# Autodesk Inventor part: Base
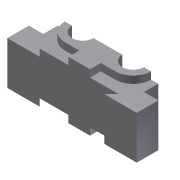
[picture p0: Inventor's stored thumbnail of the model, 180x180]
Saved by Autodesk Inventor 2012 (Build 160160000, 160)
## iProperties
Created: 2009-05
Part Number: Base
Document SubType Name: Modeling
Designer: Sham
Density: 1 g/cm^3
Material: Default
Author: Sham
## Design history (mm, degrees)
sketch "Sketch1"
  geometry: L1 (0, 0)-(27.5, 0); L2 (27.5, 0)-(22.5, -5); L3 (22.5, -5)-(45, -5); L4 (45, -5)-(45, 10); L5 (45, 10)-(35, 10); L6 (35, 10)-(35, 20); L7 (35, 20)-(-35, 20); L8 (-35, 20)-(-35, 10); L9 (-35, 10)-(-45, 10); L10 (-45, 10)-(-45, -5); L11 (-45, -5)-(-22.5, -5); L12 (-22.5, -5)-(-27.5, 0); L13 (-27.5, 0)-(0, 0); 1 further point
  constraints: 26 end point, 9 perpendicular, 5 equal length, 2 horizontal, 1 coincident, 1 other
  dimensions: "d1" = 15 distance of L9.end L10.end; "d2" = 5 distance between parallel lines of L11 L13; "d3" = 10 distance of L5.end L6.end; "d4" = 22.5 distance of L2.end L3.end; "d5" = 45 distance of L2.end L11.end; "d6" = 90 distance between parallel lines of L4 L10 (derived); "d7" = 5 horizontal distance of L1.end L2.end; "d15" = 70 distance of L6.end L7.end; "d16" = 35 distance from line of L8 point (0, 0)
extrude "Extrusion1" new body sketch "Sketch1" stored distance "d8" = 30; taper "d9" = 0 deg
sketch "Sketch2"
  geometry: L1 (-7.5, 0)-(-7.5, 7.5); L2 (-7.5, 7.5)-(-17.5, 7.5); L3 (7.5, 7.5)-(17.5, 7.5); L4 (7.5, 0)-(7.5, 7.5); L5 (-7.5, 0)-(7.5, 0); L6 (35, 20)-(-35, 20) reference; L7 (-30, 20)-(30, 20); A1 r 12.5 centre (-17.5, 20) between (-30, 20) and (-17.5, 7.5); A2 r 12.5 centre (17.5, 20) between (17.5, 7.5) and (30, 20); 2 further points
  constraints: 12 end point, 4 point on circle, 3 perpendicular, 2 centre point, 2 horizontal, 2 point on line, 2 tangent, 1 coincident, 1 collinear, 1 horizontal alignment, 1 midpoint, 1 other
  dimensions: "d10" = 15 distance of L1.start L4.start; "d11" = 35 distance of A2.centre A1.centre; "d12" = 12.5 radius of A1; "d13" = 12.5 radius of A2; "d14" = 7.5 distance of L1.start L1.end
extrude "Extrusion2" join sketch "Sketch2" stored distance "d17" = 40; taper "d18" = 0 deg
sketch "Sketch3"
  geometry: L1 (10, 20)-(10.397, 20); L2 (10, 20)-(25, 20); L3 (-25, 20)-(-10, 20); L4 (-30, 20)-(30, 20) reference; A1 r 7.5 centre (-17.5, 20) between (-25, 20) and (-10, 20); A2 r 7.5 centre (17.5, 20) between (10, 20) and (25, 20); A3 r 12.5 centre (17.5, 20) between (17.5, 7.5) and (30, 20) reference; A4 r 12.5 centre (-17.5, 20) between (-30, 20) and (-17.5, 7.5) reference; 2 further points
  constraints: 6 end point, 4 point on circle, 3 coincident, 2 centre point, 2 horizontal, 2 midpoint, 2 point on line, 1 equal radius
  dimensions: "d19" = 15 diameter of A1; "d53" = 7.5 radius of A2 (derived); "d54" = 35 distance of A1.centre A3.centre (derived)
extrude "Extrusion3" cut sketch "Sketch3" distance "d24" = 40; taper "d25" = 0 deg
hole "Hole1" diameter "d28" = 4.5; stored, may be unused: countersink angle "d32" = 90 deg, drill point angle "d34" = 118 deg; dims "d26" = 30, "d27" = 5, "d29" = 6, "d30" = 4, "d31" = 2, "d33" = 15
pattern_linear "Rectangular Pattern1" dims "d37" = 30
hole "Hole2" diameter "d40" = 4.5; stored, may be unused: countersink angle "d44" = 90 deg, drill point angle "d46" = 118 deg; dims "d38" = 5, "d39" = 7.5, "d41" = 6, "d42" = 4, "d43" = 2, "d45" = 15
pattern_linear "Rectangular Pattern2" dims "d49" = 15
body "Solid1"
